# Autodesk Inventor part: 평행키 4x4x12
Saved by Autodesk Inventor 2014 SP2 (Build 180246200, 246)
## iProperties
Created: 2024-04
Part Number: 평행키 4x4x12
Material: Generic
Document SubType Name: Modeling
Designer: Administrator
Density: 1 g/cm^3
Appearance: Default
Author: Administrator
Author: jhkim
Description: 키 및 해당 키홈
Creation Date: 2024-04-08
Sending System: Autodesk Inventor 2025
Preprocessor: ST-DEVELOPER v20
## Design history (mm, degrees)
node "평행키 4x4x121"
body "Solid1"
node "기준1"
